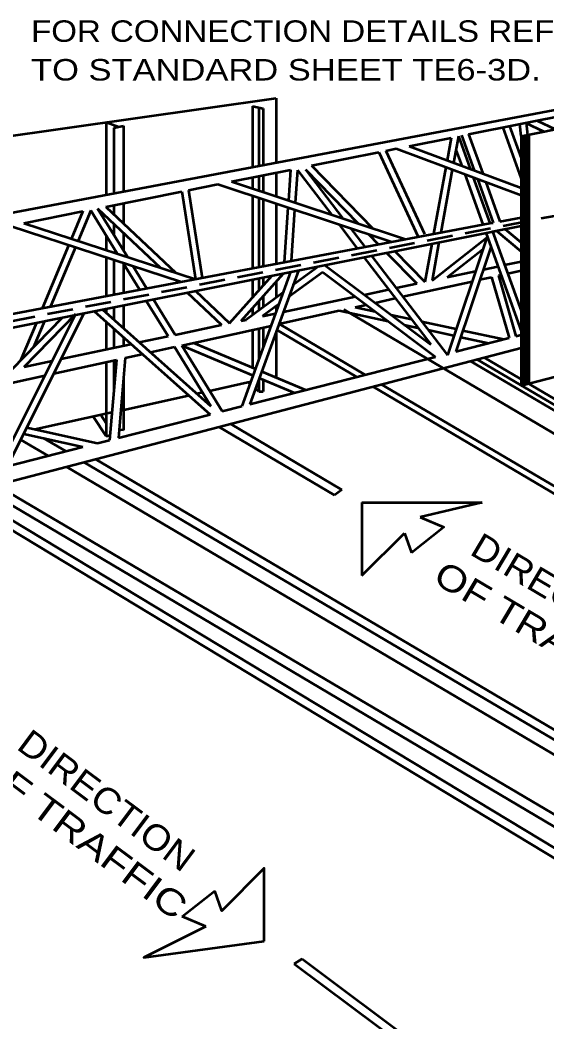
# Model space of a CAD drawing. Extents: x -68 to 612, y -58 to 382.
# Drawn here: x 416 to 477.3, y 170.3 to 286.9 of the extents above; entities that cross this region are included whole.
import ezdxf
from ezdxf.enums import TextEntityAlignment as Align

# ---------------------------------------------------------------- set-up
doc = ezdxf.new("R2010")
doc.units = 0
doc.linetypes.add('MEDIUM_DASHED', pattern=[4.5, 3, -1.5])
doc.layers.add('1', color=7, linetype='Continuous', lineweight=53)

msp = doc.modelspace()

# ---------------------------------------------------------------- linework, layer by layer
at = {"layer": '1'}
for p, q in [((468.152, 273.581), (510.134, 281.979)), ((474.259, 273.368), (504.159, 279.349)), ((402.759, 271.646), (445.759, 277.79)), ((445.759, 277.79), (445.759, 270.29)), ((443.009, 276.826), (443.009, 269.769)), ((443.009, 276.826), (444.259, 276.576)), ((443.759, 276.576), (443.759, 269.911)), ((444.259, 276.576), (444.259, 270.006)), ((426.009, 274.968), (427.447, 274.433)), ((426.009, 274.968), (426.009, 266.549)), ((426.884, 274.302), (428.009, 274.564)), ((426.884, 274.302), (426.884, 266.715)), ((428.009, 274.564), (428.009, 266.928)), ((472.117, 274.374), (474.259, 268.403)), ((472.91, 274.532), (474.259, 270.772)), ((474.259, 273.368), (474.1, 274.77)), ((474.757, 274.902), (476.891, 273.895)), ((475.054, 273.458), (474.888, 274.928)), ((476.073, 275.165), (478.208, 274.158)), ((461.225, 272.195), (466.128, 273.176)), ((466.128, 273.176), (465.646, 270.545)), ((466.972, 273.344), (466.407, 270.26)), ((466.972, 273.344), (468.337, 269.54)), ((467.34, 273.476), (468.816, 269.361)), ((468.152, 273.581), (469.797, 268.995)), ((474.259, 273.368), (474.259, 244.326)), ((474.499, 273.416), (474.499, 244.561)), ((474.672, 273.451), (474.672, 244.434)), ((474.846, 273.485), (474.846, 244.561)), ((475.019, 273.52), (475.019, 244.561)), ((475.159, 273.548), (475.159, 244.561)), ((458.511, 271.652), (459.736, 271.897)), ((459.736, 271.897), (474.259, 266.475)), ((461.225, 272.195), (474.259, 267.329)), ((466.685, 271.776), (467.356, 269.906)), ((474.326, 271.798), (474.326, 244.343)), ((474.586, 271.798), (474.586, 244.411)), ((449.859, 269.921), (457.703, 271.49)), ((457.703, 271.49), (462.304, 261.636)), ((458.511, 271.652), (463.029, 261.974)), ((440.581, 268.065), (447.444, 269.438)), ((447.444, 269.438), (447.193, 265.875)), ((448.242, 269.382), (447.976, 265.615)), ((448.242, 269.382), (452.187, 264.22)), ((449.184, 269.467), (453.534, 263.774)), ((449.184, 269.467), (455.307, 263.186)), ((449.859, 269.921), (456.957, 262.64)), ((465.499, 269.745), (464.073, 261.971)), ((466.26, 269.461), (464.916, 262.131)), ((443.009, 268.551), (443.009, 267.261)), ((443.759, 268.701), (443.759, 267.012)), ((444.259, 268.801), (444.259, 266.846)), ((445.759, 269.101), (445.759, 266.349)), ((467.709, 268.92), (469.812, 263.058)), ((468.691, 268.554), (470.608, 263.209)), ((469.17, 268.375), (470.996, 263.282)), ((435.562, 267.061), (438.995, 267.748)), ((435.562, 267.061), (437.158, 256.847)), ((438.995, 267.748), (459.212, 261.05)), ((440.581, 268.065), (460.83, 261.357)), ((470.151, 268.009), (471.792, 263.433)), ((425.952, 265.139), (434.777, 266.904)), ((434.777, 266.904), (436.368, 256.724)), ((443.009, 266.418), (443.009, 257.981)), ((443.759, 266.169), (443.759, 258.124)), ((444.259, 266.004), (444.259, 258.218)), ((424.198, 264.707), (422.722, 261.177)), ((424.198, 264.707), (427.279, 259.69)), ((424.99, 264.946), (428.453, 259.307)), ((424.99, 264.946), (432.323, 258.044)), ((425.952, 265.139), (434.109, 257.461)), ((426.884, 265.325), (426.884, 264.262)), ((428.009, 265.55), (428.009, 263.203)), ((445.759, 265.507), (445.759, 258.502)), ((447.135, 265.051), (446.684, 258.678)), ((447.918, 264.792), (447.497, 258.832)), ((416.425, 263.233), (423.288, 264.606)), ((423.288, 264.606), (421.959, 261.426)), ((471.792, 263.433), (474.259, 263.9)), ((375.293, 245.156), (470.608, 263.209)), ((414.827, 262.913), (434.736, 256.415)), ((416.425, 263.233), (436.368, 256.724)), ((426.884, 263.163), (426.884, 261.862)), ((453.049, 263.092), (455.191, 260.289)), ((454.397, 262.645), (456.07, 260.455)), ((470.608, 263.209), (470.996, 263.282)), ((470.951, 262.253), (474.259, 262.915)), ((472.388, 262.541), (474.259, 260.976)), ((420.898, 252.241), (471.382, 262.34)), ((426.009, 261.758), (426.009, 260.105)), ((428.009, 262.104), (428.009, 260.03)), ((456.52, 261.942), (457.674, 260.759)), ((463.896, 256.57), (470.282, 261.573)), ((470.312, 261.664), (465.69, 247.866)), ((470.18, 262.034), (474.259, 250.66)), ((470.951, 262.253), (474.259, 253.03)), ((471.382, 262.34), (474.259, 259.933)), ((421.65, 260.686), (418.587, 253.356)), ((422.413, 260.437), (419.528, 253.534)), ((463.865, 260.836), (463.05, 256.39)), ((464.709, 261.005), (463.896, 256.57)), ((465.674, 256.946), (469.82, 260.195)), ((470.748, 260.447), (466.675, 248.286)), ((426.009, 259.263), (426.009, 254.762)), ((426.884, 258.978), (426.884, 254.927)), ((455.978, 259.258), (463.744, 249.095)), ((456.851, 259.433), (465.69, 247.866)), ((458.621, 259.787), (462.124, 256.194)), ((459.556, 259.974), (463.05, 256.39)), ((427.925, 258.638), (429.858, 255.491)), ((428.009, 258.61), (428.009, 255.141)), ((429.099, 258.255), (430.699, 255.65)), ((448.352, 257.733), (442.712, 242.154)), ((450.702, 258.182), (447.722, 255.994)), ((451.428, 258.348), (463.744, 249.095)), ((469.874, 257.835), (471.558, 258.192)), ((472.347, 258.359), (474.259, 258.764)), ((472.704, 257.366), (474.259, 257.71)), ((440.353, 251.583), (445.305, 257.123)), ((441.677, 251.864), (446.612, 257.385)), ((447.435, 257.549), (441.774, 241.915)), ((443.009, 256.664), (443.009, 254.555)), ((443.759, 256.814), (443.759, 255.394)), ((444.259, 256.914), (444.259, 255.953)), ((451.176, 257.537), (447.233, 254.642)), ((451.176, 257.537), (464.299, 247.678)), ((465.674, 256.946), (468.965, 257.643)), ((469.478, 256.655), (470.832, 256.953)), ((470.832, 256.953), (472.888, 249.875)), ((471.614, 257.126), (471.916, 257.193)), ((471.614, 257.126), (473.663, 250.074)), ((445.759, 256.431), (445.759, 254.552)), ((456.017, 254.901), (458.849, 255.501)), ((459.716, 255.684), (462.124, 256.194)), ((460.489, 254.672), (468.567, 256.454)), ((431.491, 254.36), (434.02, 250.242)), ((435.405, 255.143), (439.401, 251.382)), ((436.368, 255.335), (440.353, 251.583)), ((446.563, 255.143), (442.268, 251.989)), ((444.259, 254.753), (444.259, 253.451)), ((446.605, 252.908), (454.977, 254.681)), ((457.267, 253.961), (459.628, 254.482)), ((425.558, 253.173), (438.176, 241.946)), ((426.009, 253.353), (426.009, 252.837)), ((426.884, 253.438), (426.884, 251.993)), ((428.009, 253.663), (428.009, 250.992)), ((430.655, 254.193), (433.19, 250.066)), ((443.009, 253.354), (443.009, 252.533)), ((443.759, 254.193), (443.759, 253.084)), ((446.074, 253.791), (444.168, 252.391)), ((445.759, 253.56), (445.759, 252.921)), ((446.094, 251.496), (453.103, 253.042)), ((453.103, 253.042), (458.804, 251.806)), ((453.651, 253.163), (535.086, 205.073)), ((454.974, 253.455), (456.238, 253.734)), ((454.974, 253.455), (457.272, 252.957)), ((375.302, 243.12), (420.898, 252.241)), ((413.438, 234.665), (422.369, 252.535)), ((414.527, 234.944), (423.425, 252.746)), ((415.055, 246.226), (420.898, 252.241)), ((416.459, 246.523), (422.443, 252.683)), ((424.575, 252.976), (438.072, 240.967)), ((441.677, 251.864), (442.268, 251.989)), ((444.168, 252.391), (445.684, 252.712)), ((459.144, 252.551), (461.493, 252.042)), ((474.259, 244.326), (504.159, 252.141)), ((417.867, 251.634), (416.023, 247.223)), ((418.813, 251.824), (417.545, 248.789)), ((426.009, 251.701), (426.009, 248.546)), ((426.884, 250.922), (426.884, 248.731)), ((434.02, 250.242), (439.401, 251.382)), ((434.783, 249.001), (445.169, 251.292)), ((443.009, 250.815), (443.009, 246.412)), ((443.759, 250.981), (443.759, 247.397)), ((444.259, 251.091), (444.259, 248.778)), ((445.759, 250.843), (455.103, 245.325)), ((446.114, 251.501), (456.128, 245.587)), ((460.676, 251.4), (462.242, 251.06)), ((462.699, 251.78), (466.71, 250.91)), ((463.449, 250.799), (466.454, 250.147)), ((467.497, 250.74), (472.243, 249.71)), ((428.009, 249.921), (428.009, 248.969)), ((429.846, 249.358), (433.19, 250.066)), ((445.759, 250.571), (445.759, 245.256)), ((466.675, 248.286), (472.888, 249.875)), ((467.241, 249.976), (470.511, 249.267)), ((473.663, 250.074), (474.259, 250.226)), ((375.388, 222.867), (474.259, 248.711)), ((420.771, 247.436), (428.873, 249.152)), ((431.149, 248.199), (433.956, 248.818)), ((433.956, 248.818), (438.176, 241.946)), ((434.783, 249.001), (439.493, 241.331)), ((434.783, 249.001), (443.078, 245.515)), ((436.137, 249.299), (443.351, 246.268)), ((416.459, 246.523), (419.708, 247.211)), ((419.913, 245.72), (427.173, 247.322)), ((427.173, 247.322), (426.39, 237.979)), ((426.884, 247.258), (426.884, 243.873)), ((428.196, 247.547), (427.416, 238.241)), ((428.196, 247.547), (430.184, 247.986)), ((442.712, 242.154), (464.299, 247.678)), ((469.138, 247.372), (536.555, 207.56)), ((469.96, 247.587), (536.862, 208.08)), ((426.009, 247.065), (426.009, 238.43)), ((468.381, 247.174), (536.273, 207.082)), ((407.088, 242.891), (418.846, 245.485)), ((428.009, 245.32), (428.009, 239.119)), ((443.759, 245.019), (443.759, 243.637)), ((443.816, 245.205), (447.911, 243.484)), ((444.089, 245.958), (449.194, 243.813)), ((444.259, 245.019), (444.259, 243.637)), ((445.439, 245.363), (445.759, 245.434)), ((438.023, 243.725), (442.813, 244.783)), ((442.717, 244.52), (442.494, 244.709)), ((443.759, 243.637), (443.368, 243.968)), ((457.006, 244.201), (531.083, 200.457)), ((458.025, 244.467), (529.679, 202.154)), ((427.684, 241.44), (435.58, 243.185)), ((436.544, 243.398), (437.196, 243.542)), ((443.759, 243.637), (444.259, 243.637)), ((439.493, 241.331), (441.774, 241.915)), ((417.7, 239.234), (426.661, 241.214)), ((426.009, 238.43), (424.476, 240.731)), ((426.009, 239.938), (425.352, 240.925)), ((427.416, 238.241), (438.072, 240.967)), ((416.774, 239.439), (424.994, 237.621)), ((428.009, 239.119), (427.494, 239.18)), ((439.105, 239.522), (452.535, 231.554)), ((440.465, 239.877), (453.402, 232.202)), ((416.061, 238.012), (419.223, 236.145)), ((416.405, 238.701), (423.276, 237.182)), ((418.706, 238.192), (421.282, 236.672)), ((424.994, 237.621), (426.39, 237.979)), ((426.009, 238.43), (426.438, 238.552)), ((414.527, 234.944), (423.276, 237.182)), ((424.768, 235.774), (514.52, 182.773)), ((421.36, 234.883), (512.987, 180.775)), ((423.405, 235.418), (513.778, 182.05)), ((411.694, 232.357), (509.936, 174.113)), ((413.181, 232.745), (509.936, 175.609)), ((453.402, 232.202), (452.535, 231.554)), ((408.38, 231.491), (506.63, 172.091)), ((409.73, 231.843), (507.099, 172.976)), ((455.735, 230.715), (455.735, 222.215)), ((455.735, 230.715), (469.735, 230.715)), ((469.735, 230.715), (462.518, 229.002)), ((455.735, 222.215), (460.685, 227.165)), ((460.685, 227.165), (461.503, 224.87)), ((434.847, 182.531), (438.616, 185.504)), ((437.601, 181.371), (434.847, 182.531)), ((448.807, 177.588), (447.875, 177.036)), ((448.807, 177.588), (476.147, 157.138)), ((447.875, 177.036), (475.215, 156.586))]:
    msp.add_line(p, q, dxfattribs=at)
for points in [[(359.251, 253.915), (359.997, 254.047), (510.13, 282.482)], [(462.518, 229.002), (465.272, 227.842), (461.503, 224.87)], [(444.384, 179.658), (444.384, 188.158), (439.434, 183.208), (438.616, 185.504)], [(437.601, 181.371), (430.36, 177.774), (444.384, 179.658)]]:
    msp.add_lwpolyline(points, dxfattribs=at)
at = {"layer": '1', "linetype": 'MEDIUM_DASHED'}
msp.add_lwpolyline([(375.294, 244.216), (392.667, 247.516), (478.145, 264.087)], dxfattribs=at)

# ---------------------------------------------------------------- texts
at = {"layer": '1'}
for s, width, p in [('FOR CONNECTION DETAILS REFER', 1.15, (417.251, 284.329)), ('TO STANDARD SHEET TE6-3D.', 1.2, (417.251, 279.829))]:
    msp.add_text(s, height=2.5, dxfattribs=dict(at, width=width)).set_placement(p)
for s, rotation, width, p in [('DIRECTION', 329.321, 1.1, (478.585, 218.557)), ('OF TRAFFIC', 329.321, 1.2, (476.034, 214.257)), ('DIRECTION', 323.204, 1.1, (425.145, 194.842)), ('OF TRAFFIC', 323.204, 1.25, (422.15, 190.838))]:
    msp.add_text(s, height=3, rotation=rotation, dxfattribs=dict(at, width=width)).set_placement(p, align=Align.CENTER)

doc.saveas('drawing.dxf')
